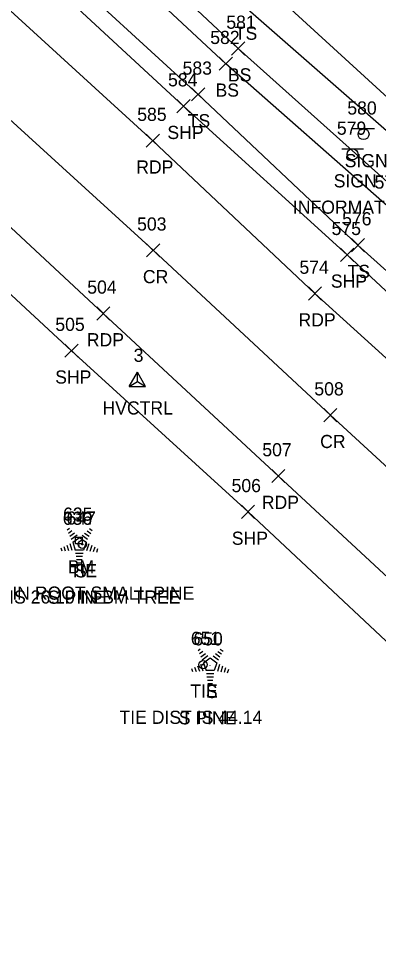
# Model space of a CAD drawing. Extents: x 1611034 to 1613847, y 761049 to 763902.
# Drawn here: x 1611761.1 to 1611815.8, y 763048.6 to 763188 of the extents above; entities that cross this region are included whole.
import ezdxf

# ---------------------------------------------------------------- set-up
doc = ezdxf.new("R2010")
doc.units = 0
for name, color, linetype in [('C_A', 7, 'Continuous'), ('C_C', 7, 'Continuous'), ('C_I', 7, 'Continuous'), ('CBP', 7, 'Continuous'), ('CPBM', 7, 'Continuous'), ('CPSM', 7, 'Continuous'), ('L_A', 7, 'Continuous'), ('L_C', 7, 'Continuous'), ('L_I', 7, 'Continuous'), ('L_TIC', 7, 'Continuous'), ('LAWA', 7, 'Continuous'), ('LELB', 7, 'Continuous'), ('LTC', 7, 'Continuous'), ('P_A', 7, 'Continuous'), ('P_I', 7, 'Continuous'), ('P_TIC', 7, 'Continuous'), ('PET', 7, 'Continuous'), ('PRC', 7, 'Continuous'), ('PSP', 7, 'Continuous'), ('S_A', 7, 'Continuous'), ('S_C', 7, 'Continuous'), ('S_I', 7, 'Continuous'), ('SSGN', 7, 'Continuous')]:
    doc.layers.add(name, color=color, linetype=linetype)

msp = doc.modelspace()

# ---------------------------------------------------------------- linework, layer by layer
at = {"layer": 'CBP'}
for centre, radius in [((1611770.79, 763108.07), 0.625), ((1611770.79, 763108.07), 0.0833), ((1611789.11, 763089.79), 0.625), ((1611789.11, 763089.79), 0.0833)]:
    msp.add_circle(centre, radius, dxfattribs=at)
at = {"layer": 'CPBM'}
for p, q in [((1611769.77, 763108.16), (1611769.77, 763109.16)), ((1611769.77, 763109.16), (1611770.77, 763109.16)), ((1611770.77, 763109.16), (1611770.77, 763108.16)), ((1611770.77, 763108.16), (1611769.77, 763108.16)), ((1611770.27, 763108.66), (1611770.27, 763108.66)), ((1611770.27, 763108.66), (1611770.27, 763108.66))]:
    msp.add_line(p, q, dxfattribs=at)
at = {"layer": 'CPSM'}
for p, q in [((1611777.91, 763132.07), (1611779.16, 763134.24)), ((1611780.41, 763132.07), (1611779.16, 763134.24)), ((1611779.16, 763132.8), (1611779.16, 763134.24)), ((1611777.91, 763132.07), (1611779.16, 763132.8)), ((1611779.16, 763132.8), (1611779.16, 763132.8)), ((1611779.16, 763132.8), (1611780.41, 763132.07)), ((1611777.91, 763132.07), (1611780.41, 763132.07))]:
    msp.add_line(p, q, dxfattribs=at)
at = {"layer": 'L_TIC'}
for points in [[(1611793.46, 763182.41), (1611795.46, 763184.41)], [(1611795.46, 763182.41), (1611793.46, 763184.41)], [(1611791.58, 763180.1), (1611793.58, 763182.1)], [(1611793.58, 763180.1), (1611791.58, 763182.1)], [(1611787.39, 763175.44), (1611789.39, 763177.44)], [(1611789.39, 763175.44), (1611787.39, 763177.44)], [(1611811.66, 763152.54), (1611813.66, 763154.54)], [(1611813.66, 763152.54), (1611811.66, 763154.54)]]:
    msp.add_lwpolyline(points, dxfattribs=at)
at = {"layer": 'LAWA'}
msp.add_lwpolyline([(1611776.19, 763209.71), (1611798.35, 763193.21), (1611821.91, 763171.59), (1611835.23, 763154.9), (1611840.73, 763150.36), (1611854.8, 763137.66), (1611869.74, 763122.61), (1611885.36, 763108.52), (1611898.9, 763094.55), (1611920.73, 763076.3), (1611936.34, 763060.75), (1611959.95, 763037.9), (1611979.24, 763021.14), (1611992.68, 763010.08), (1612014.52, 762988.49), (1612021.56, 762990.5), (1612027.56, 763011.05)], dxfattribs=at)
at = {"layer": 'LELB'}
for points in [[(1611776.19, 763209.71), (1611795.53, 763189.74), (1611818.61, 763169.56), (1611835.23, 763154.9)], [(1612018.61, 762964.73), (1611994.45, 762990.34), (1611965, 763017.91), (1611936.07, 763051.1), (1611910.74, 763076.87), (1611888.16, 763094.11), (1611862.22, 763121.84), (1611845.65, 763138.15), (1611819.53, 763160.99), (1611794.46, 763183.41), (1611771.91, 763204.52)], [(1612017.14, 762963.27), (1611992.31, 762988.18), (1611962.87, 763016.31), (1611931.63, 763047.56), (1611908.18, 763073.24), (1611886.96, 763093.2), (1611860.29, 763119.05), (1611842.79, 763135.64), (1611817.54, 763159.12), (1611792.58, 763181.1), (1611769.85, 763202.31)], [(1612014.39, 762960.1), (1611988.81, 762984.91), (1611960.67, 763014.03), (1611928.51, 763044.56), (1611903.94, 763068.78), (1611882.15, 763089), (1611856.04, 763113.65), (1611837.67, 763131.07), (1611812.66, 763153.54), (1611788.39, 763176.44), (1611765.16, 763197.77)]]:
    msp.add_lwpolyline(points, dxfattribs=at)
at = {"layer": 'LTC'}
for p, q in [((1611768.48, 763110.25), (1611768.84, 763110.51)), ((1611768.69, 763109.78), (1611769.22, 763110.17)), ((1611771.51, 763110.14), (1611772.06, 763109.74)), ((1611771.88, 763110.49), (1611772.3, 763110.19)), ((1611768.9, 763109.32), (1611769.61, 763109.83)), ((1611769.11, 763108.85), (1611769.99, 763109.49)), ((1611769.34, 763108.4), (1611770.35, 763109.13)), ((1611770.35, 763109.13), (1611771.35, 763108.41)), ((1611770.77, 763109.45), (1611771.58, 763108.86)), ((1611771.14, 763109.79), (1611771.82, 763109.3)), ((1611767.52, 763107.53), (1611767.67, 763107.06)), ((1611767.97, 763107.75), (1611768.18, 763107.09)), ((1611768.43, 763107.96), (1611768.7, 763107.13)), ((1611768.88, 763108.18), (1611769.21, 763107.16)), ((1611769.34, 763108.4), (1611769.72, 763107.2)), ((1611771.35, 763108.41), (1611770.95, 763107.2)), ((1611771.78, 763108.14), (1611771.45, 763107.1)), ((1611772.23, 763107.89), (1611771.94, 763107)), ((1611772.67, 763107.64), (1611772.44, 763106.91)), ((1611773.12, 763107.39), (1611772.93, 763106.81)), ((1611770.95, 763107.2), (1611769.72, 763107.2)), ((1611770.92, 763106.7), (1611769.77, 763106.7)), ((1611770.83, 763106.2), (1611769.84, 763106.2)), ((1611770.75, 763105.7), (1611769.92, 763105.7)), ((1611770.67, 763105.2), (1611769.99, 763105.2)), ((1611788.36, 763091.92), (1611788.71, 763092.18)), ((1611791.75, 763092.16), (1611792.17, 763091.86)), ((1611788.57, 763091.46), (1611789.09, 763091.84)), ((1611788.77, 763090.99), (1611789.48, 763091.5)), ((1611788.98, 763090.52), (1611789.86, 763091.16)), ((1611789.21, 763090.07), (1611790.22, 763090.8)), ((1611790.22, 763090.8), (1611791.22, 763090.08)), ((1611790.64, 763091.12), (1611791.45, 763090.53)), ((1611791.01, 763091.46), (1611791.69, 763090.97)), ((1611791.38, 763091.81), (1611791.93, 763091.41)), ((1611787.39, 763089.2), (1611787.54, 763088.73)), ((1611787.84, 763089.42), (1611788.06, 763088.77)), ((1611788.3, 763089.63), (1611788.57, 763088.8)), ((1611788.75, 763089.85), (1611789.09, 763088.83)), ((1611789.21, 763090.07), (1611789.6, 763088.88)), ((1611791.22, 763090.08), (1611790.83, 763088.88)), ((1611791.65, 763089.81), (1611791.32, 763088.77)), ((1611792.1, 763089.56), (1611791.81, 763088.67)), ((1611792.54, 763089.31), (1611792.31, 763088.58)), ((1611790.83, 763088.88), (1611789.6, 763088.88)), ((1611790.79, 763088.38), (1611789.64, 763088.38)), ((1611790.7, 763087.88), (1611789.72, 763087.88)), ((1611792.99, 763089.06), (1611792.8, 763088.48)), ((1611790.62, 763087.38), (1611789.79, 763087.38)), ((1611790.54, 763086.88), (1611789.86, 763086.88))]:
    msp.add_line(p, q, dxfattribs=at)
at = {"layer": 'P_TIC'}
for points in [[(1611785.17, 763173.66), (1611787.17, 763175.66)], [(1611787.17, 763173.66), (1611785.17, 763175.66)], [(1611780.49, 763168.41), (1611782.49, 763170.41)], [(1611782.49, 763168.41), (1611780.49, 763170.41)], [(1611780.55, 763151.75), (1611782.55, 763153.75)], [(1611782.55, 763151.75), (1611780.55, 763153.75)], [(1611810.01, 763151.07), (1611812.01, 763153.07)], [(1611812.01, 763151.07), (1611810.01, 763153.07)], [(1611805.13, 763145.18), (1611807.13, 763147.18)], [(1611807.13, 763145.18), (1611805.13, 763147.18)], [(1611772.98, 763142.16), (1611774.98, 763144.16)], [(1611774.98, 763142.16), (1611772.98, 763144.16)], [(1611768.14, 763136.5), (1611770.14, 763138.5)], [(1611770.14, 763136.5), (1611768.14, 763138.5)], [(1611807.47, 763126.7), (1611809.47, 763128.7)], [(1611809.47, 763126.7), (1611807.47, 763128.7)], [(1611799.57, 763117.45), (1611801.57, 763119.45)], [(1611801.57, 763117.45), (1611799.57, 763119.45)], [(1611794.96, 763112), (1611796.96, 763114)], [(1611796.96, 763112), (1611794.96, 763114)]]:
    msp.add_lwpolyline(points, dxfattribs=at)
at = {"layer": 'PET'}
for points in [[(1612007.41, 762953.69), (1611981.88, 762978.72), (1611953.4, 763007), (1611921.8, 763038.1), (1611897.05, 763061.61), (1611875.73, 763082.09), (1611849.32, 763106.5), (1611830.38, 763124.18), (1611806.13, 763146.18), (1611781.49, 763169.41), (1611758.07, 763190.79)], [(1611742.95, 763171.95), (1611773.98, 763143.16), (1611800.57, 763118.45), (1611832.55, 763088.78), (1611862.37, 763060.94), (1611895.49, 763029.35), (1611927.37, 762998.83), (1611963.34, 762963.21), (1611989.07, 762936.88)]]:
    msp.add_lwpolyline(points, dxfattribs=at)
at = {"layer": 'PRC'}
msp.add_lwpolyline([(1611750.53, 763181.03), (1611781.55, 763152.75), (1611808.47, 763127.7), (1611840.68, 763098.05), (1611871.03, 763069.71), (1611903.68, 763038.16), (1611935.64, 763007.53), (1611970.73, 762973.2), (1611998.37, 762945.17)], dxfattribs=at)
at = {"layer": 'PSP'}
for points in [[(1612013.06, 762958.69), (1611987.98, 762983.85), (1611959.05, 763012.61), (1611927.06, 763043.5), (1611902.53, 763067.25), (1611880.81, 763087.35), (1611854.34, 763111.86), (1611835.7, 763129.09), (1611811.01, 763152.07), (1611786.17, 763174.66), (1611763.42, 763195.74)], [(1611737.63, 763166.68), (1611769.14, 763137.5), (1611795.96, 763113), (1611827.31, 763083.61), (1611857.87, 763055.56), (1611890.74, 763023.79), (1611921.91, 762994.17), (1611958.53, 762957.84), (1611984.49, 762931.79)]]:
    msp.add_lwpolyline(points, dxfattribs=at)
at = {"layer": 'SSGN'}
for p, q in [((1611811.86, 763171.24), (1611815.19, 763171.24)), ((1611813.5, 763170.4), (1611813.5, 763170.4)), ((1611810.19, 763168.16), (1611813.52, 763168.16)), ((1611811.83, 763167.33), (1611811.83, 763167.33))]:
    msp.add_line(p, q, dxfattribs=at)
for centre in [(1611813.5, 763170.4), (1611811.83, 763167.33)]:
    msp.add_circle(centre, 0.833, dxfattribs=at)

# ---------------------------------------------------------------- texts
at = {"layer": 'C_A'}
for s, p in [('HVCTRL', (1611773.85, 763127.8)), ('BM', (1611768.58, 763103.66)), ('TIE', (1611768.87, 763103.07)), ('TIE', (1611787.19, 763084.79))]:
    msp.add_text(s, height=2, dxfattribs=at).set_placement(p)
at = {"layer": 'C_C'}
for s, p in [('RR SPIKE IN ROOT SMALL PINE', (1611746.93, 763099.66)), ('TIE DIST IS 26.10 IN BM TREE', (1611747.94, 763099.07)), ('TIE DIST IS 44.14', (1611776.43, 763080.79))]:
    msp.add_text(s, height=2, dxfattribs=at).set_placement(p)
at = {"layer": 'C_I'}
for s, p in [('3', (1611778.59, 763135.8)), ('635', (1611767.86, 763111.66)), ('647', (1611768.38, 763111.07)), ('651', (1611787.27, 763092.79))]:
    msp.add_text(s, height=2, dxfattribs=at).set_placement(p)
at = {"layer": 'L_A'}
for s, p in [('TS', (1611793.94, 763184.74)), ('BS', (1611792.9, 763178.41)), ('BS', (1611791.02, 763176.1)), ('TS', (1611786.8, 763171.44)), ('TS', (1611811.07, 763148.54)), ('S', (1611769.67, 763103.04)), ('S', (1611789.55, 763084.71))]:
    msp.add_text(s, height=2, dxfattribs=at).set_placement(p)
at = {"layer": 'L_C'}
for p in [(1611765.56, 763099.04), (1611785.44, 763080.71)]:
    msp.add_text('S PINE', height=2, dxfattribs=at).set_placement(p)
at = {"layer": 'L_I'}
for s, p in [('581', (1611792.66, 763186.41)), ('582', (1611790.22, 763184.1)), ('583', (1611786.02, 763179.44)), ('577', (1611815.18, 763162.12)), ('576', (1611810.25, 763156.54)), ('636', (1611767.82, 763111.04)), ('650', (1611787.66, 763092.71))]:
    msp.add_text(s, height=2, dxfattribs=at).set_placement(p)
at = {"layer": 'LTC'}
for p in [(1611770.23, 763108.15), (1611790.1, 763089.82)]:
    msp.add_text('.', height=1.04, rotation=270, dxfattribs=at).set_placement(p)
at = {"layer": 'P_A'}
for s, p in [('SHP', (1611783.71, 763169.66)), ('RDP', (1611778.98, 763164.41)), ('CR', (1611779.99, 763147.75)), ('SHP', (1611808.54, 763147.07)), ('RDP', (1611803.62, 763141.18)), ('RDP', (1611771.47, 763138.16)), ('SHP', (1611766.67, 763132.5)), ('CR', (1611806.91, 763122.7)), ('RDP', (1611798.05, 763113.45)), ('SHP', (1611793.49, 763108))]:
    msp.add_text(s, height=2, dxfattribs=at).set_placement(p)
at = {"layer": 'P_I'}
for s, p in [('584', (1611783.81, 763177.66)), ('585', (1611779.13, 763172.41)), ('503', (1611779.11, 763155.75)), ('575', (1611808.65, 763155.07)), ('574', (1611803.77, 763149.18)), ('504', (1611771.54, 763146.16)), ('505', (1611766.69, 763140.5)), ('508', (1611806.03, 763130.7)), ('507', (1611798.13, 763121.45)), ('506', (1611793.46, 763116))]:
    msp.add_text(s, height=2, dxfattribs=at).set_placement(p)
at = {"layer": 'S_A'}
for p in [(1611810.64, 763165.38), (1611808.97, 763162.31)]:
    msp.add_text('SIGN', height=2, dxfattribs=at).set_placement(p)
at = {"layer": 'S_C'}
msp.add_text('INFORMATION', height=2, dxfattribs=at).set_placement((1611802.77, 763158.31))
at = {"layer": 'S_I'}
for s, p in [('580', (1611811.04, 763173.38)), ('579', (1611809.45, 763170.31))]:
    msp.add_text(s, height=2, dxfattribs=at).set_placement(p)

doc.saveas('drawing.dxf')
